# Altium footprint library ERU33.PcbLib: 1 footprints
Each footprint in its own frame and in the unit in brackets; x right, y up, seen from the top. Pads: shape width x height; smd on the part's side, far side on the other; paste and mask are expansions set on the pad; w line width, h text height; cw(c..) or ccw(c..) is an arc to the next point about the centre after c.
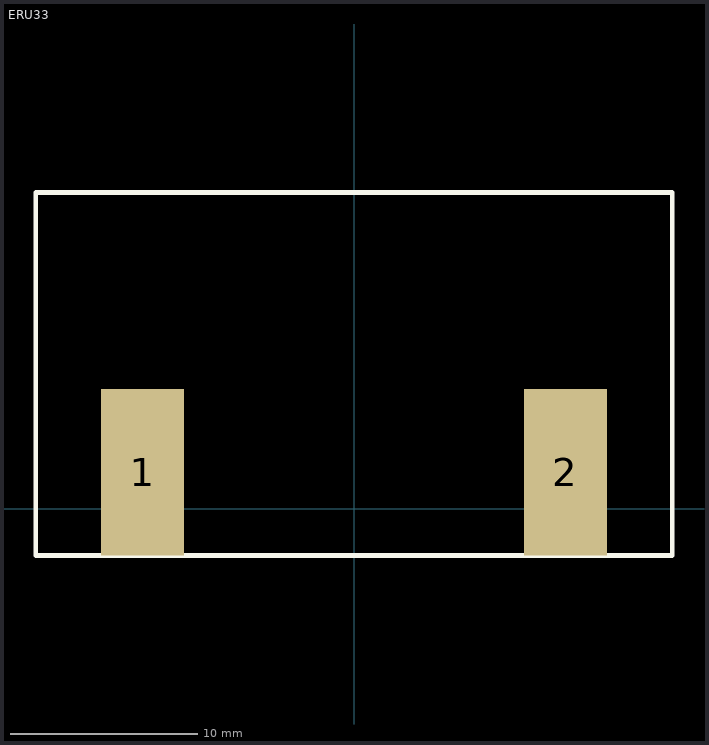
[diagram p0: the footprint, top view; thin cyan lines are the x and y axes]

## ERU33 [mm]
pads (2):
  rect 4.45x8.9 smd: 1(-11.3,1.95) 2(11.3,1.95)
Top Overlay:
  lines w0.254: -17,-2.5 17,-2.5 17,16.9 -17,16.9 -17,-2.5
M5 Assembly Top:
  text ".Designator" at -1.8,-0.514 h1.02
